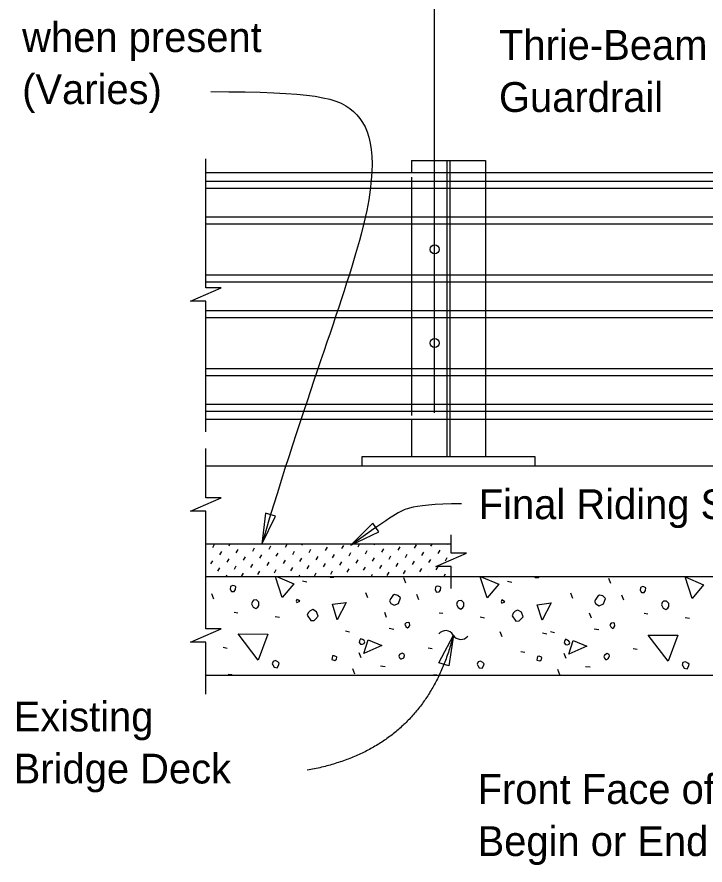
# Model space of a CAD drawing. Extents: x 21587 to 21659.1, y 56116.2 to 56157.3.
# Drawn here: x 21606.04 to 21610.68, y 56132.1 to 56137.83 of the extents above; entities that cross this region are included whole.
import ezdxf

# ---------------------------------------------------------------- set-up
doc = ezdxf.new("R2010")
doc.units = 0
for name, color, linetype in [('AdhocPoint_dp', 7, 'Continuous'), ('Border', 7, 'Continuous'), ('Patterning', 7, 'Continuous'), ('PlotBorder_dp', 7, 'Continuous'), ('SheetBorder_dp', 7, 'Continuous'), ('TextMisc', 7, 'Continuous')]:
    doc.layers.add(name, color=color, linetype=linetype)

msp = doc.modelspace()

# ---------------------------------------------------------------- linework, layer by layer
at = {"layer": 'AdhocPoint_dp'}
for p, q in [((21607.3117, 56134.8009), (21613.4854, 56134.8009)), ((21608.9696, 56134.2699), (21607.3116, 56134.2699)), ((21613.4854, 56134.0509), (21607.3117, 56134.0509)), ((21607.3117, 56133.3843), (21613.4854, 56133.3843))]:
    msp.add_line(p, q, dxfattribs=at)
at = {"layer": 'Border'}
for p, q in [((21608.7018, 56136.8635), (21609.2018, 56136.8635)), ((21608.7018, 56136.8635), (21608.7018, 56136.7802)), ((21609.2018, 56136.8635), (21609.2018, 56136.7802)), ((21619.5663, 56136.7801), (21607.3117, 56136.7801)), ((21607.3117, 56136.7246), (21619.5663, 56136.7246)), ((21607.3117, 56136.6764), (21619.5663, 56136.6764)), ((21607.3117, 56136.4835), (21619.5663, 56136.4835)), ((21607.3117, 56136.4353), (21619.5663, 56136.4353)), ((21607.3117, 56136.0914), (21619.5663, 56136.0914)), ((21607.3117, 56136.0431), (21619.5663, 56136.0431)), ((21607.3117, 56135.8503), (21619.5663, 56135.8503)), ((21607.3117, 56135.8022), (21619.5663, 56135.8022)), ((21607.3117, 56135.4582), (21619.5663, 56135.4582)), ((21607.3117, 56135.41), (21619.5663, 56135.41)), ((21607.3117, 56135.2172), (21619.5663, 56135.2172)), ((21607.3117, 56135.169), (21619.5663, 56135.169)), ((21619.5663, 56135.1134), (21607.3117, 56135.1134)), ((21608.7018, 56135.1135), (21608.7018, 56134.8635)), ((21609.2018, 56135.1134), (21609.2018, 56134.8635)), ((21608.3685, 56134.8635), (21609.5351, 56134.8635)), ((21608.3685, 56134.801), (21608.3685, 56134.8635)), ((21608.7018, 56134.8635), (21609.2018, 56134.8635)), ((21609.5351, 56134.8635), (21609.5351, 56134.801)), ((21608.3685, 56134.801), (21609.5351, 56134.801))]:
    msp.add_line(p, q, dxfattribs=at)
for centre in [(21608.858, 56136.2634), (21608.858, 56135.6303)]:
    msp.add_circle(centre, 0.0312, dxfattribs=at)
at = {"layer": 'Patterning'}
for p, q in [((21608.9414, 56134.8635), (21608.9414, 56136.8635)), ((21608.9622, 56134.8635), (21608.9622, 56136.8635)), ((21609.2018, 56136.7801), (21609.2018, 56135.1134)), ((21608.7018, 56136.7516), (21608.7018, 56135.1398))]:
    msp.add_line(p, q, dxfattribs=at)
at = {"layer": 'PlotBorder_dp'}
msp.add_line((21608.858, 56135.1577), (21608.858, 56143.2258), dxfattribs=at)
for points in [[(21607.3117, 56135.0303), (21607.3117, 56135.9135), (21607.2084, 56135.9135), (21607.3117, 56135.9585), (21607.4151, 56136.0035), (21607.3117, 56136.0035), (21607.3117, 56136.8765)], [(21607.3117, 56134.0229), (21607.3117, 56134.493), (21607.2084, 56134.493), (21607.3117, 56134.538), (21607.4151, 56134.583), (21607.3117, 56134.583), (21607.3117, 56134.9175)], [(21608.9697, 56133.972), (21608.9697, 56134.1198), (21608.8664, 56134.1198), (21608.9697, 56134.1648), (21609.073, 56134.2098), (21608.9697, 56134.2098), (21608.9697, 56134.3343)], [(21607.3117, 56133.2578), (21607.3117, 56133.6084), (21607.2084, 56133.6084), (21607.3117, 56133.6534), (21607.4151, 56133.6984), (21607.3117, 56133.6984), (21607.3117, 56134.0229)]]:
    msp.add_lwpolyline(points, dxfattribs=at)
for points in [[(21607.6902, 56134.2707), (21607.7828, 56134.4606), (21607.7151, 56134.4805)], [(21608.2911, 56134.2633), (21608.4817, 56134.3543), (21608.4411, 56134.412)], [(21608.9843, 56133.6565), (21608.9539, 56133.4475), (21608.8867, 56133.4692)]]:
    msp.add_lwpolyline(points, close=True, dxfattribs=at)
for centre, start, end in [((21608.9319, 56133.6269), 30.00813, 141.73535), ((21609.0352, 56133.6865), 210.00813, 321.73535)]:
    msp.add_arc(centre, 0.0596, start, end, dxfattribs=at)
for points, degree in [([(21607.346, 56137.3295), (21608.025, 56137.3274), (21608.4126, 56137.2724), (21608.5135, 56136.5948), (21607.9729, 56135.2323), (21607.6902, 56134.2708)], 3), ([(21609.0397, 56134.5436), (21608.8463, 56134.5415), (21608.6579, 56134.5211), (21608.5865, 56134.4713), (21608.2911, 56134.2634)], 3), ([(21608.9843, 56133.6565), (21608.7894, 56132.8844), (21607.9969, 56132.7426)], 2)]:
    msp.add_open_spline(points, degree=degree, dxfattribs=at)
at = {"layer": 'TextMisc'}
for p, q in [((21607.3586, 56134.2474), (21607.3715, 56134.2698)), ((21607.4692, 56134.2604), (21607.4747, 56134.2699)), ((21607.6287, 56134.2245), (21607.6416, 56134.2469)), ((21607.7393, 56134.2375), (21607.7523, 56134.2599)), ((21607.8499, 56134.2504), (21607.8612, 56134.2699)), ((21607.9606, 56134.2634), (21607.9643, 56134.2699)), ((21608.12, 56134.2275), (21608.133, 56134.2499)), ((21608.2307, 56134.2405), (21608.2436, 56134.2629)), ((21608.3413, 56134.2535), (21608.3508, 56134.2699)), ((21608.4519, 56134.2664), (21608.4539, 56134.2699)), ((21608.6114, 56134.2306), (21608.6244, 56134.253)), ((21608.722, 56134.2435), (21608.735, 56134.2659)), ((21608.8327, 56134.2565), (21608.8404, 56134.2699)), ((21608.9433, 56134.2695), (21608.9436, 56134.2699)), ((21607.4074, 56134.1986), (21607.4204, 56134.221)), ((21607.518, 56134.2116), (21607.531, 56134.234)), ((21607.6775, 56134.1757), (21607.6905, 56134.1981)), ((21607.7881, 56134.1887), (21607.8011, 56134.211)), ((21607.8988, 56134.2016), (21607.9117, 56134.224)), ((21608.0094, 56134.2146), (21608.0224, 56134.237)), ((21608.1689, 56134.1787), (21608.1818, 56134.2011)), ((21608.2795, 56134.1917), (21608.2925, 56134.2141)), ((21608.3901, 56134.2046), (21608.4031, 56134.227)), ((21608.5008, 56134.2176), (21608.5137, 56134.24)), ((21608.5496, 56134.1688), (21608.5626, 56134.1912)), ((21608.6602, 56134.1817), (21608.6732, 56134.2041)), ((21608.7709, 56134.1947), (21608.7838, 56134.2171)), ((21608.8815, 56134.2077), (21608.8945, 56134.23)), ((21607.3456, 56134.1368), (21607.3586, 56134.1592)), ((21607.4562, 56134.1498), (21607.4692, 56134.1722)), ((21607.5669, 56134.1627), (21607.5798, 56134.1851)), ((21607.6157, 56134.1139), (21607.6287, 56134.1363)), ((21607.7263, 56134.1269), (21607.7393, 56134.1492)), ((21607.837, 56134.1398), (21607.8499, 56134.1622)), ((21607.9476, 56134.1528), (21607.9606, 56134.1752)), ((21608.0582, 56134.1657), (21608.0712, 56134.1881)), ((21608.1071, 56134.1169), (21608.12, 56134.1393)), ((21608.2177, 56134.1299), (21608.2307, 56134.1523)), ((21608.3283, 56134.1428), (21608.3413, 56134.1652)), ((21608.439, 56134.1558), (21608.4519, 56134.1782)), ((21608.5984, 56134.1199), (21608.6114, 56134.1423)), ((21608.7091, 56134.1329), (21608.722, 56134.1553)), ((21608.8197, 56134.1459), (21608.8327, 56134.1682)), ((21608.9303, 56134.1588), (21608.9433, 56134.1812)), ((21607.3944, 56134.088), (21607.4074, 56134.1104)), ((21607.5051, 56134.1009), (21607.518, 56134.1233)), ((21607.5539, 56134.0521), (21607.5669, 56134.0745)), ((21607.6645, 56134.0651), (21607.6775, 56134.0874)), ((21607.7752, 56134.078), (21607.7881, 56134.1004)), ((21607.8858, 56134.091), (21607.8988, 56134.1134)), ((21607.9964, 56134.1039), (21608.0094, 56134.1263)), ((21608.0453, 56134.0551), (21608.0582, 56134.0775)), ((21608.1559, 56134.0681), (21608.1689, 56134.0905)), ((21608.2665, 56134.081), (21608.2795, 56134.1034)), ((21608.3772, 56134.094), (21608.3901, 56134.1164)), ((21608.4878, 56134.107), (21608.5008, 56134.1294)), ((21608.5366, 56134.0581), (21608.5496, 56134.0805)), ((21608.6473, 56134.0711), (21608.6602, 56134.0935)), ((21608.7579, 56134.0841), (21608.7709, 56134.1065)), ((21608.8685, 56134.097), (21608.8815, 56134.1194)), ((21608.9792, 56134.11), (21608.9793, 56134.1102)), ((21607.4501, 56134.0509), (21607.4562, 56134.0615)), ((21607.8366, 56134.0509), (21607.837, 56134.0516)), ((21607.9397, 56134.0509), (21607.9476, 56134.0645)), ((21607.9652, 56134.0238), (21607.9935, 56134.0167)), ((21608.3262, 56134.0509), (21608.3283, 56134.0546)), ((21608.4293, 56134.0509), (21608.439, 56134.0676)), ((21608.6635, 56134.0079), (21608.6494, 56134.0432)), ((21608.8158, 56134.0509), (21608.8197, 56134.0576)), ((21608.919, 56134.0509), (21608.9303, 56134.0706)), ((21609.3499, 56134.0203), (21609.3782, 56134.0132)), ((21610.0482, 56134.0043), (21610.034, 56134.0397)), ((21607.3666, 56133.8989), (21607.3524, 56133.9343)), ((21608.4072, 56133.9071), (21608.393, 56133.9425)), ((21608.7513, 56133.8954), (21608.7371, 56133.9307)), ((21609.7919, 56133.9036), (21609.7777, 56133.9389)), ((21610.1359, 56133.8918), (21610.1218, 56133.9272)), ((21607.5045, 56133.8105), (21607.5292, 56133.807)), ((21608.5327, 56133.7745), (21608.5203, 56133.8081)), ((21608.8892, 56133.807), (21608.9139, 56133.8034)), ((21609.9174, 56133.771), (21609.905, 56133.8046)), ((21610.2738, 56133.8034), (21610.2986, 56133.7999)), ((21607.7802, 56133.7822), (21607.8103, 56133.7769)), ((21609.1649, 56133.7787), (21609.195, 56133.7734)), ((21610.5496, 56133.7752), (21610.5797, 56133.7699)), ((21608.2552, 56133.6844), (21608.2834, 56133.6773)), ((21608.5515, 56133.7027), (21608.5816, 56133.6974)), ((21609.3134, 56133.6443), (21609.301, 56133.6779)), ((21609.6398, 56133.6808), (21609.6681, 56133.6738)), ((21609.9362, 56133.6991), (21609.9662, 56133.6938)), ((21609.5874, 56133.6709), (21609.6157, 56133.6638)), ((21607.4302, 56133.5736), (21607.4567, 56133.5683)), ((21608.8149, 56133.5701), (21608.8414, 56133.5648)), ((21610.1996, 56133.5666), (21610.2261, 56133.5613)), ((21608.3612, 56133.5018), (21608.3488, 56133.5354)), ((21609.4407, 56133.5453), (21609.4672, 56133.54)), ((21609.7459, 56133.4982), (21609.7335, 56133.5318)), ((21608.4914, 56133.4481), (21608.5232, 56133.4446)), ((21609.8761, 56133.4446), (21609.9079, 56133.4411)), ((21608.3188, 56133.3922), (21608.3046, 56133.4275)), ((21609.7035, 56133.3886), (21609.6893, 56133.424))]:
    msp.add_line(p, q, dxfattribs=at)
for points in [[(21607.828, 56133.9113), (21607.7825, 56134.0509)], [(21607.7964, 56134.0509), (21607.9058, 56134.0032), (21607.828, 56133.9113)], [(21608.1516, 56134.0509), (21608.1526, 56134.0485), (21608.1502, 56134.0509)], [(21608.1526, 56134.0485), (21608.1738, 56134.0485), (21608.1762, 56134.0509)], [(21609.2127, 56133.9077), (21609.1661, 56134.0509)], [(21609.173, 56134.0509), (21609.2904, 56133.9997), (21609.2127, 56133.9077)], [(21609.5348, 56134.0509), (21609.5373, 56134.045), (21609.5338, 56134.0485)], [(21609.5373, 56134.045), (21609.5585, 56134.045), (21609.5644, 56134.0509)], [(21610.5973, 56133.9042), (21610.5496, 56134.0509), (21610.6751, 56133.9961), (21610.5973, 56133.9042)], [(21607.4762, 56133.9661), (21607.485, 56133.9502), (21607.5045, 56133.9519), (21607.5133, 56133.9643), (21607.5151, 56133.9838), (21607.5027, 56133.9891), (21607.4939, 56133.9908), (21607.4833, 56133.9873), (21607.4797, 56133.9838), (21607.4762, 56133.9661)], [(21608.8609, 56133.9625), (21608.8697, 56133.9466), (21608.8892, 56133.9484), (21608.898, 56133.9608), (21608.8998, 56133.9802), (21608.8874, 56133.9855), (21608.8785, 56133.9873), (21608.8679, 56133.9838), (21608.8644, 56133.9802), (21608.8609, 56133.9625)], [(21610.2455, 56133.959), (21610.2544, 56133.9431), (21610.2738, 56133.9449), (21610.2827, 56133.9572), (21610.2844, 56133.9767), (21610.2721, 56133.982), (21610.2632, 56133.9838), (21610.2526, 56133.9802), (21610.2491, 56133.9767), (21610.2455, 56133.959)], [(21608.561, 56133.87), (21608.584, 56133.8576), (21608.614, 56133.87), (21608.6264, 56133.9071), (21608.6087, 56133.9248), (21608.5857, 56133.9301), (21608.5751, 56133.923), (21608.5627, 56133.9036), (21608.5539, 56133.8877), (21608.561, 56133.87)], [(21609.9457, 56133.8665), (21609.9686, 56133.8541), (21609.9987, 56133.8665), (21610.0111, 56133.9036), (21609.9934, 56133.9213), (21609.9704, 56133.9266), (21609.9598, 56133.9195), (21609.9474, 56133.9), (21609.9386, 56133.8841), (21609.9457, 56133.8665)], [(21607.6211, 56133.8671), (21607.6318, 56133.8459), (21607.6494, 56133.8353), (21607.6636, 56133.8459), (21607.6706, 56133.8565), (21607.6706, 56133.8777), (21607.6547, 56133.8936), (21607.6353, 56133.8918), (21607.6265, 56133.883), (21607.6211, 56133.8671)], [(21607.927, 56133.8759), (21607.9464, 56133.8848), (21607.9393, 56133.8918), (21607.927, 56133.8971), (21607.9217, 56133.8848), (21607.927, 56133.8759)], [(21608.2003, 56133.7604), (21608.1668, 56133.8647), (21608.2605, 56133.8771), (21608.2003, 56133.7604)], [(21609.0058, 56133.8635), (21609.0164, 56133.8423), (21609.0341, 56133.8317), (21609.0483, 56133.8423), (21609.0553, 56133.8529), (21609.0553, 56133.8742), (21609.0394, 56133.8901), (21609.02, 56133.8883), (21609.0111, 56133.8795), (21609.0058, 56133.8635)], [(21609.3116, 56133.8724), (21609.3311, 56133.8812), (21609.324, 56133.8883), (21609.3116, 56133.8936), (21609.3063, 56133.8812), (21609.3116, 56133.8724)], [(21609.585, 56133.7569), (21609.5514, 56133.8612), (21609.6451, 56133.8735), (21609.585, 56133.7569)], [(21610.3905, 56133.86), (21610.4011, 56133.8388), (21610.4188, 56133.8282), (21610.4329, 56133.8388), (21610.44, 56133.8494), (21610.44, 56133.8706), (21610.4241, 56133.8865), (21610.4046, 56133.8848), (21610.3958, 56133.8759), (21610.3905, 56133.86)], [(21607.9977, 56133.7911), (21608.0207, 56133.7539), (21608.0436, 56133.7557), (21608.0525, 56133.7646), (21608.0719, 56133.784), (21608.0596, 56133.814), (21608.0348, 56133.8282), (21608.0171, 56133.8211), (21608.003, 56133.807), (21607.9977, 56133.7911)], [(21609.3824, 56133.7875), (21609.4053, 56133.7504), (21609.4283, 56133.7522), (21609.4372, 56133.761), (21609.4566, 56133.7805), (21609.4442, 56133.8105), (21609.4195, 56133.8247), (21609.4018, 56133.8176), (21609.3877, 56133.8034), (21609.3824, 56133.7875)], [(21608.6629, 56133.7151), (21608.6735, 56133.7044), (21608.6841, 56133.7115), (21608.6912, 56133.7221), (21608.6876, 56133.7398), (21608.6788, 56133.7416), (21608.6664, 56133.7398), (21608.6558, 56133.7292), (21608.6629, 56133.7151)], [(21610.0476, 56133.7115), (21610.0582, 56133.7009), (21610.0688, 56133.708), (21610.0758, 56133.7186), (21610.0723, 56133.7363), (21610.0635, 56133.738), (21610.0511, 56133.7363), (21610.0405, 56133.7257), (21610.0476, 56133.7115)], [(21607.6653, 56133.487), (21607.531, 56133.6638), (21607.7307, 56133.662), (21607.6653, 56133.487)], [(21608.3577, 56133.596), (21608.3701, 56133.5942), (21608.3824, 56133.5995), (21608.386, 56133.6101), (21608.3807, 56133.619), (21608.3701, 56133.626), (21608.3577, 56133.6313), (21608.3506, 56133.6172), (21608.3471, 56133.6066), (21608.3577, 56133.596)], [(21608.38, 56133.5312), (21608.4083, 56133.6231), (21608.502, 56133.586), (21608.38, 56133.5312)], [(21609.7424, 56133.5925), (21609.7547, 56133.5907), (21609.7671, 56133.596), (21609.7706, 56133.6066), (21609.7653, 56133.6154), (21609.7547, 56133.6225), (21609.7424, 56133.6278), (21609.7353, 56133.6137), (21609.7318, 56133.6031), (21609.7424, 56133.5925)], [(21609.7647, 56133.5277), (21609.793, 56133.6196), (21609.8867, 56133.5825), (21609.7647, 56133.5277)], [(21610.4347, 56133.4799), (21610.3003, 56133.6567), (21610.5001, 56133.655), (21610.4347, 56133.4799)], [(21608.1639, 56133.4905), (21608.1833, 56133.4852), (21608.1957, 56133.4941), (21608.1974, 56133.5065), (21608.1939, 56133.51), (21608.1798, 56133.5171), (21608.1674, 56133.5153), (21608.1656, 56133.5029), (21608.1639, 56133.4905)], [(21608.6275, 56133.4959), (21608.6346, 56133.4959), (21608.6487, 56133.5029), (21608.654, 56133.5188), (21608.6523, 56133.5277), (21608.6381, 56133.5347), (21608.6205, 56133.5241), (21608.6169, 56133.5135), (21608.6205, 56133.5029), (21608.6275, 56133.4959)], [(21609.5485, 56133.487), (21609.568, 56133.4817), (21609.5803, 56133.4905), (21609.5821, 56133.5029), (21609.5786, 56133.5065), (21609.5644, 56133.5135), (21609.5521, 56133.5118), (21609.5503, 56133.4994), (21609.5485, 56133.487)], [(21610.0122, 56133.4923), (21610.0193, 56133.4923), (21610.0334, 56133.4994), (21610.0387, 56133.5153), (21610.0369, 56133.5241), (21610.0228, 56133.5312), (21610.0051, 56133.5206), (21610.0016, 56133.51), (21610.0051, 56133.4994), (21610.0122, 56133.4923)], [(21607.7643, 56133.4552), (21607.7732, 56133.4393), (21607.7944, 56133.4357), (21607.8032, 56133.4517), (21607.8068, 56133.4658), (21607.7979, 56133.4746), (21607.782, 56133.4835), (21607.7661, 56133.4782), (21607.7608, 56133.4623), (21607.7643, 56133.4552)], [(21609.149, 56133.4517), (21609.1579, 56133.4357), (21609.1791, 56133.4322), (21609.1879, 56133.4481), (21609.1914, 56133.4623), (21609.1826, 56133.4711), (21609.1667, 56133.4799), (21609.1508, 56133.4746), (21609.1455, 56133.4587), (21609.149, 56133.4517)], [(21610.5337, 56133.4481), (21610.5425, 56133.4322), (21610.5637, 56133.4287), (21610.5726, 56133.4446), (21610.5761, 56133.4587), (21610.5673, 56133.4676), (21610.5514, 56133.4764), (21610.5355, 56133.4711), (21610.5302, 56133.4552), (21610.5337, 56133.4481)], [(21607.4896, 56133.3843), (21607.4886, 56133.388), (21607.4656, 56133.3898), (21607.4637, 56133.3843)], [(21608.8733, 56133.3843), (21608.8732, 56133.3845), (21608.8503, 56133.3862), (21608.8496, 56133.3843)]]:
    msp.add_lwpolyline(points, dxfattribs=at)

# ---------------------------------------------------------------- texts
at = {"layer": 'PlotBorder_dp'}
for s, p in [('when present', (21606.0715, 56137.5973)), ('Thrie-Beam ', (21609.2926, 56137.5444)), ('(Varies)', (21606.0715, 56137.2453)), ('Guardrail', (21609.2926, 56137.1924)), ('Existing ', (21606.0143, 56133.0052)), ('Bridge Deck', (21606.0143, 56132.6532)), ('Front Face of Backwall &', (21609.1479, 56132.5148)), ('Begin or End Bridge', (21609.1479, 56132.1628))]:
    msp.add_text(s, height=0.2016, dxfattribs=at).set_placement(p)
at = {"layer": 'SheetBorder_dp'}
msp.add_text('Final Riding Surface', height=0.2016, dxfattribs=at).set_placement((21609.1559, 56134.44))

doc.saveas('drawing.dxf')
